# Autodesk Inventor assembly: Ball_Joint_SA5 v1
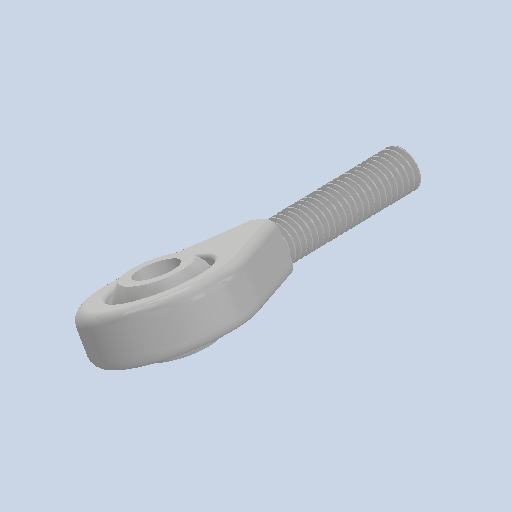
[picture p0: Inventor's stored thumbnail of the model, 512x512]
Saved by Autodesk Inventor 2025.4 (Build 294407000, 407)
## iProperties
Created: 2026-09
Part Number: Ball_Joint_SA5 v1
Document SubType Name: Assembly
Designer: AdminForWorker
Title: rotula v1
Author: AdminForWorker
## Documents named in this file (3)
- c:\worker\convert-fusion-r05-cosv3\tmp\job-1\19\temp\files\ca3d996b-dda0-445d-8bee-12a194174ca8\rotula v1_1.iam
- c:\worker\convert-fusion-r05-cosv3\tmp\job-1\19\temp\files\ca3d996b-dda0-445d-8bee-12a194174ca8\Component33.ipt
- c:\worker\convert-fusion-r05-cosv3\tmp\job-1\19\temp\files\ca3d996b-dda0-445d-8bee-12a194174ca8\Component34.ipt
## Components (2 placed, 2 different names)
1. Component33:1
2. Component34:1
